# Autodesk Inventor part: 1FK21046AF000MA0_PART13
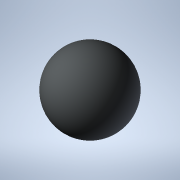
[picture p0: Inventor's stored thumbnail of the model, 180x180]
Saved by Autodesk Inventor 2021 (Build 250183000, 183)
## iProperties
Created: 2025-04
Part Number: 1FK21046AF000MA0_PART13
Material: Generic
Catalog Web Link: www.3dfindit.com
Description: -Servo synchronous motor
Document SubType Name: Modeling
Designer: psAdmin
Mass: 0.137258 g
Surface Area: 1.2868 cm^2
Volume: 0.137258 cm^3
Density: 1 g/cm^3
Appearance: PSOLRGB-212-217-219
Category: PARTsolutions
Title: 1FK21046AF000MA0_PART13
Author: Cadenas PARTsolutions
Comments: Servo synchronous motor
Sending System: PARTsolutions
Preprocessor: ST-DEVELOPER v19.3
PSOL_IDENT_0: {$CADENAS_DATA/23d-libs/siemens_ag/_cat_/1c/1f/1fk21046af000ma0.prj},216 {VTYP=3D},{NB=1FK21046AF000
PSOL_IDENT_1: MA0_PART13},{LINA=1FK21046AF000MA0_PART13},{NN=1FK21046AF000MA0_PART13},{NOPRJ=TRUE},{DATE=19.08.202
PSOL_IDENT_2: 5 14:00:28},{GEOMDATE=30.07.2025 02:02:08},{VERSION=},{LINEID=10},{WBVAR=},{WBNUMERIC=}  {NB=1FK2104
PSOL_IDENT_3: 6AF000MA0_PART13},{LINA=1FK21046AF000MA0_PART13},{KT=DUMMY},{PREVIEW=../../../_pool_/cb/72/p_d211_xx
PSOL_IDENT_4: _00434j.png},{DESCSHORT=SIMOTICS S-1FK2 HD, SINAMICS S210 3AC 400V-480V, 3.2 Nm, 3000 rpm},{DESCLONG=
PSOL_IDENT_5: SIMOTICS S-1FK2 HD servo motor M0=3.2 Nm; PN = 1 kW at nN=3000 rpm (380-480 V); PN = 0.5 kW at nN=15
PSOL_IDENT_6: 00 rpm (200-240 V); degree of protection IP64; cylindrical shaft D19x40mm; absolute encoder 22-bit +
PSOL_IDENT_7: 12-bit multiturn (encoder AM22DQC); with OCC interface; plug size M17, rotatable; SIMOTICS S-1FK2 s
PSOL_IDENT_8: ervomotorfor a wide range of uses in industrial environments. SIMOTICS S‑1FK2 servomotors are compac
PSOL_IDENT_9: t synchronous motors with a high dynamic performance that set themselves apart as a result of their
PSOL_IDENT_10: high power density, degree of protection and overload capability. The motors are available in two va
PSOL_IDENT_11: riants: as High Dynamic variant (highest dynamic performance as a result of the low intrinsic moment
PSOL_IDENT_12: of inertia for applications demanding a high dynamic performance with low moved masses) - and as Co
PSOL_IDENT_13: mpact variant (precise and stable closed-loop control for medium up to large moved masses as a resul
PSOL_IDENT_14: t of a medium intrinsic moment of inertia). SIMOTICSS‑1FK2 servomotors fully exploit their strengths
PSOL_IDENT_15: in a system with the SINAMICSS210 frequency converter and simple connection using the one cable con
PSOL_IDENT_16: nection (OCC). Advantages include the short control and positioning times, fast and precise correcti
PSOL_IDENT_17: on of disturbing quantities as well as stable control with a high dynamic performance. The servo mot
PSOL_IDENT_18: ors can be configured to address a wide range of requirements. For example with and without holding
PSOL_IDENT_19: brake, IP64 or IP65 degree of protection, singleturn or multiturn absolute encoders - to name just a
PSOL_IDENT_20: few. Further, the servomotors are available in different shaft heights extending from 20 to 100. A
PSOL_IDENT_21: shaft sealing ring is available to achieve an IP65 degree of protection and for subsequent mounting
PSOL_IDENT_22: at the motor or as spare part. SIMOTICS - the optimum motor for each and every motion control applic
PSOL_IDENT_23: ation.},{INTNO=195125049666},{SUPPLIERALTNO=1FK2104-6AF00-0MA0},{MANUID=1FK21046AF000MA0},{MANUNAME=
PSOL_IDENT_24: Siemens},{MANUTYPEDESC=Synchronous motor 1FK2-HD 3.2 NM},{AAU732=SIMOTICS},{AAO057=S-1FK2},{AAU734=S
PSOL_IDENT_25: IMOTICS S-1FK2 HD servo motor M0=3.2 Nm; PN = 1 kW at nN=3000 rpm (380-480 V); PN = 0.5 kW at nN=150
PSOL_IDENT_26: 0 rpm (200-240 V); degree of protection IP64; cylindrical shaft D19x40mm; absolute encoder 22-bit +
PSOL_IDENT_27: 12-bit multiturn (encoder AM22DQC); with OCC interface; plug size M17, rotatable;},{AAW338=Synchrono
PSOL_IDENT_28: us motor 1FK2-HD 3.2 NM},{AAO742=SIMOTICS},{AAO663=4042948694374},{NOCUPEROU=1},{PRICEQUANTITY=1},{Q
PSOL_IDENT_29: UANTITYMIN=1},{QUANTITYINT=1},{CTN=85015220},{COO=DE},{AAO676=1FK2104-6AF00-0MA0},{AAO677=Siemens AG
PSOL_IDENT_30: },{ORDERUNIT=C62},{CONTENTUNIT=C62}
NB: 1FK21046AF000MA0_PART13
NT: Servo synchronous motor
NBSYN: $MANUID._PART13
LINA: 1FK21046AF000MA0_PART13
CATALOG: SIEMENS
PREVIEW: ../../../_pool_/cb/72/p_d211_xx_00434j.png
DESCSHORT: SIMOTICS S-1FK2 HD, SINAMICS S210 3AC 400V-480V, 3.2 Nm, 3000 rpm
DESCLONG: SIMOTICS S-1FK2 HD servo motor M0=3.2 Nm; PN = 1 kW at nN=3000 rpm (380-480 V); PN = 0.5 kW at nN=1500 rpm (200-240 V); degree of protection IP64; cylindrical s
INTNO: 195125049666
SUPPLIERALTNO: 1FK2104-6AF00-0MA0
MANUID: 1FK21046AF000MA0
MANUNAME: Siemens
MANUTYPEDESC: Synchronous motor 1FK2-HD 3.2 NM
AAU732: SIMOTICS
AAO057: S-1FK2
AAU734: SIMOTICS S-1FK2 HD servo motor M0=3.2 Nm; PN = 1 kW at nN=3000 rpm (380-480 V); PN = 0.5 kW at nN=1500 rpm (200-240 V); degree of protection IP64; cylindrical s
AAW338: Synchronous motor 1FK2-HD 3.2 NM
AAO742: SIMOTICS
AAO663: 4042948694374.0
NOCUPEROU: 1
PRICEQUANTITY: 1
QUANTITYMIN: 1
QUANTITYINT: 1
CTN: 85015220
COO: DE
ARTICLENO: 1FK21046AF000MA0_PART13
BOMINFO: 1FK21046AF000MA0_PART13
CREATOR: CADENAS GmbH
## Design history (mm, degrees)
feature "2025_04_17_15_39_11_0412"
body "Solid1"
